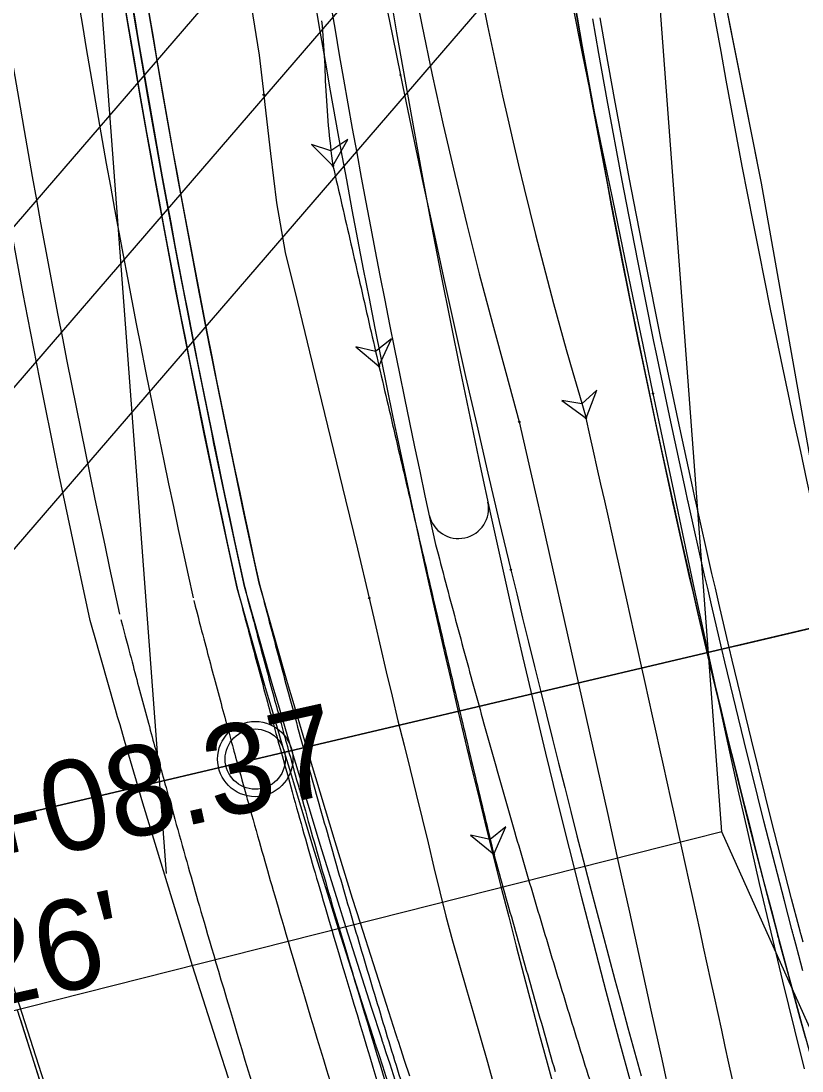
# Model space of a CAD drawing. Extents: x -70 to 701944, y -4 to 666871.
# Drawn here: x 668167.6 to 668219.5, y 656196.7 to 656266.5 of the extents above; entities that cross this region are included whole.
import ezdxf

# ---------------------------------------------------------------- set-up
doc = ezdxf.new("R2010")
doc.units = 0
for name, color, linetype in [('R_Detour', 7, 'Continuous'), ('R_Drive', 7, 'Continuous'), ('R_Horz Alg', 7, 'Continuous'), ('R_Horz Alg Annot', 7, 'Continuous'), ('R_No Plot', 7, 'Continuous'), ('R_Proposed Road', 7, 'Continuous'), ('R_Striping', 7, 'Continuous'), ('R_Water', 7, 'Continuous'), ('T_Indications', 7, 'Continuous'), ('T_Vehicle Path Lt Major', 7, 'Continuous'), ('T_Vehicle Path Rt', 7, 'Continuous')]:
    doc.layers.add(name, color=color, linetype=linetype)

msp = doc.modelspace()

# ---------------------------------------------------------------- linework, layer by layer
at = {"layer": 'R_Detour'}
msp.add_line((668141.731, 656207.682), (668219.062, 656225.912), dxfattribs=at)
at = {"layer": 'R_Drive'}
msp.add_lwpolyline([(668180.793, 656161.438), (668178.785, 656166.887), (668177.31, 656170.972), (668176.8, 656172.4), (668174.873, 656177.884), (668173.732, 656181.194), (668172.97, 656183.43), (668171.127, 656188.939), (668170.905, 656189.612), (668170.293, 656191.475), (668169.304, 656194.526), (668167.54, 656200.075)], dxfattribs=at)
at = {"layer": 'R_Horz Alg'}
for p, q in [((668214.129, 656212.597), (668204.795, 656337.586)), ((668265.354, 656098.207), (668214.129, 656212.597))]:
    msp.add_line(p, q, dxfattribs=at)
msp.add_lwpolyline([(668215.102, 656224.978), (668228.728, 656228.191)], dxfattribs=at)
msp.add_arc((668919.004, 656390.918), 716.197, 184.270523, 204.123313, dxfattribs=at)
at = {"layer": 'R_Horz Alg Annot'}
msp.add_lwpolyline([(668214.129, 656212.597), (668025.36, 656164.842)], dxfattribs=at)
at = {"layer": 'R_No Plot'}
for p, q in [((668177.231, 656209.842), (668160.778, 656430.175)), ((668146.592, 656218.335), (668259.536, 656349.509))]:
    msp.add_line(p, q, dxfattribs=at)
for points in [[(668203.487, 656355.108), (668251.852, 656358.719), (668253.161, 656341.197), (668253.893, 656332.226), (668254.707, 656323.663), (668256.989, 656304.018), (668259.175, 656288.746), (668262.093, 656271.387), (668265.097, 656255.918), (668267.006, 656246.759), (668268.493, 656237.565), (668221.915, 656226.584), (668216.775, 656255.73), (668213.367, 656272.838), (668209.96, 656289.947), (668208.341, 656303.042), (668205.828, 656325.201), (668204.769, 656337.932)], [(668145.584, 656319.648), (668148.917, 656289.832), (668153.337, 656260.517), (668160.437, 656224.08), (668163.658, 656212.851), (668221.915, 656226.584), (668216.775, 656255.73), (668209.96, 656289.947), (668206.722, 656316.137), (668205.828, 656325.201), (668149.946, 656320.05)], [(668163.658, 656212.851), (668174.905, 656177.818), (668188.213, 656142.348), (668200.781, 656111.402), (668251.57, 656131.168), (668244.19, 656150.993), (668237.799, 656169.607), (668229.783, 656196.07), (668221.915, 656226.584)]]:
    msp.add_lwpolyline(points, close=True, dxfattribs=at)
msp.add_circle((668183.124, 656217.44), 2.5, dxfattribs=at)
at = {"layer": 'R_Proposed Road'}
for points in [[(668219.702, 656198.856), (668219.335, 656200.197), (668218.975, 656201.524), (668218.715, 656202.488), (668218.621, 656202.836), (668218.549, 656203.105), (668218.274, 656204.134), (668218.077, 656204.876), (668217.947, 656205.365), (668217.934, 656205.415), (668217.921, 656205.463), (668217.916, 656205.483), (668217.913, 656205.492), (668217.908, 656205.512), (668217.882, 656205.61), (668217.817, 656205.855), (668217.315, 656207.769), (668215.955, 656213.059), (668215.547, 656214.68), (668214.636, 656218.36), (668213.356, 656223.671), (668213.155, 656224.519), (668212.464, 656227.477), (668212.237, 656228.464), (668212.116, 656228.991), (668212.011, 656229.451), (668210.916, 656234.32), (668210.901, 656234.391), (668210.735, 656235.142), (668209.757, 656239.658), (668208.784, 656244.293), (668208.638, 656245.004), (668207.559, 656250.359), (668206.806, 656254.223), (668206.52, 656255.722), (668205.522, 656261.093), (668204.967, 656264.18), (668204.564, 656266.471), (668203.647, 656271.856)], [(668192.426, 656196.101), (668192.08, 656197.151), (668191.831, 656197.909), (668191.667, 656198.41), (668191.651, 656198.461), (668191.635, 656198.51), (668191.628, 656198.53), (668191.625, 656198.54), (668191.618, 656198.56), (668191.586, 656198.66), (668191.504, 656198.91), (668190.869, 656200.866), (668189.145, 656206.277), (668188.625, 656207.935), (668187.46, 656211.703), (668185.816, 656217.143), (668185.557, 656218.013), (668184.664, 656221.046), (668184.369, 656222.059), (668184.212, 656222.599), (668184.076, 656223.071), (668182.649, 656228.068), (668182.629, 656228.141), (668182.412, 656228.913), (668181.395, 656233.609), (668180.383, 656238.429), (668180.231, 656239.17), (668179.109, 656244.739), (668178.326, 656248.757), (668178.029, 656250.316), (668176.99, 656255.901), (668176.413, 656259.112), (668175.995, 656261.494), (668175.041, 656267.095)], [(668193.392, 656196.359), (668193.046, 656197.409), (668192.797, 656198.166), (668192.634, 656198.665), (668192.617, 656198.717), (668192.601, 656198.765), (668192.595, 656198.785), (668192.592, 656198.795), (668192.585, 656198.815), (668192.552, 656198.915), (668192.471, 656199.165), (668191.837, 656201.119), (668190.114, 656206.522), (668189.595, 656208.178), (668188.431, 656211.94), (668186.789, 656217.374), (668186.531, 656218.243), (668185.638, 656221.272), (668185.344, 656222.283), (668185.187, 656222.822), (668185.05, 656223.294), (668183.626, 656228.284), (668183.605, 656228.357), (668183.389, 656229.128), (668182.373, 656233.818), (668181.363, 656238.631), (668181.21, 656239.371), (668180.09, 656244.932), (668179.308, 656248.945), (668179.011, 656250.502), (668177.974, 656256.08), (668177.398, 656259.287), (668176.98, 656261.666), (668176.027, 656267.259)], [(668191.943, 656195.971), (668191.597, 656197.022), (668191.348, 656197.781), (668191.184, 656198.282), (668191.167, 656198.333), (668191.151, 656198.382), (668191.145, 656198.402), (668191.141, 656198.412), (668191.135, 656198.432), (668191.102, 656198.532), (668191.021, 656198.782), (668190.386, 656200.74), (668188.66, 656206.154), (668188.14, 656207.814), (668186.975, 656211.584), (668185.33, 656217.028), (668185.071, 656217.899), (668184.177, 656220.934), (668183.882, 656221.947), (668183.725, 656222.487), (668183.588, 656222.96), (668182.161, 656227.96), (668182.141, 656228.033), (668181.924, 656228.805), (668180.906, 656233.505), (668179.894, 656238.328), (668179.741, 656239.069), (668178.618, 656244.642), (668177.835, 656248.663), (668177.537, 656250.223), (668176.499, 656255.812), (668175.921, 656259.025), (668175.502, 656261.409), (668174.548, 656267.013)], [(668219.515, 656203.364), (668219.24, 656204.391), (668219.043, 656205.132), (668218.914, 656205.621), (668218.9, 656205.671), (668218.888, 656205.719), (668218.882, 656205.738), (668218.88, 656205.748), (668218.875, 656205.768), (668218.849, 656205.865), (668218.784, 656206.11), (668218.283, 656208.021), (668216.925, 656213.305), (668216.517, 656214.923), (668215.607, 656218.598), (668214.329, 656223.901), (668214.129, 656224.749), (668213.439, 656227.703), (668213.211, 656228.688), (668213.091, 656229.214), (668212.986, 656229.674), (668211.893, 656234.536), (668211.877, 656234.607), (668211.712, 656235.357), (668210.735, 656239.866), (668209.764, 656244.495), (668209.617, 656245.206), (668208.54, 656250.553), (668207.788, 656254.412), (668207.503, 656255.909), (668206.506, 656261.272), (668205.952, 656264.355), (668205.55, 656266.643)], [(668219.526, 656205.261), (668219.397, 656205.749), (668219.384, 656205.799), (668219.371, 656205.847), (668219.366, 656205.866), (668219.363, 656205.876), (668219.358, 656205.895), (668219.332, 656205.993), (668219.268, 656206.237), (668218.766, 656208.147), (668217.41, 656213.427), (668217.002, 656215.045), (668216.093, 656218.717), (668214.815, 656224.016), (668214.615, 656224.863), (668213.926, 656227.815), (668213.699, 656228.8), (668213.578, 656229.325), (668213.473, 656229.785), (668212.381, 656234.644), (668212.365, 656234.714), (668212.2, 656235.464), (668211.224, 656239.971), (668210.253, 656244.596), (668210.107, 656245.306), (668209.03, 656250.65), (668208.279, 656254.506), (668207.994, 656256.002), (668206.998, 656261.361), (668206.444, 656264.442), (668206.042, 656266.728)], [(668181.353, 656196.231), (668180.71, 656198.214), (668178.965, 656203.701), (668178.44, 656205.384), (668177.262, 656209.204), (668175.599, 656214.722), (668175.337, 656215.604), (668174.438, 656218.681), (668174.138, 656219.707), (668173.977, 656220.254), (668173.841, 656220.734), (668172.397, 656225.801), (668172.376, 656225.875), (668172.157, 656226.657), (668171.126, 656231.419), (668170.1, 656236.306), (668169.945, 656237.057), (668168.808, 656242.704), (668168.014, 656246.778), (668167.713, 656248.359), (668166.66, 656254.022)], [(668169.099, 656195.184), (668167.332, 656200.758)]]:
    msp.add_lwpolyline(points, dxfattribs=at)
for radius in [707.197, 725.197]:
    msp.add_arc((668919.004, 656390.918), radius, 184.270523, 204.123313, dxfattribs=at)
at = {"layer": 'R_Striping'}
for centre, radius, start, end in [((668919.004, 656390.918), 737.197, 184.194321, 200.430569), ((668919.004, 656390.918), 741.197, 184.194564, 192.404344), ((668196.632, 656234.102), 2, 192.88532, 11.92337)]:
    msp.add_arc(centre, radius, start, end, dxfattribs=at)
msp.add_open_spline([(668195.109, 656231.702), (668195.55, 656230.027), (668196.43, 656226.678), (668197.795, 656221.667), (668199.192, 656216.667), (668200.624, 656211.678), (668202.091, 656206.7), (668203.592, 656201.735), (668205.127, 656196.781), (668206.697, 656191.84), (668208.301, 656186.91), (668209.94, 656181.994), (668211.612, 656177.091), (668213.318, 656172.201), (668215.058, 656167.324), (668216.831, 656162.461), (668218.638, 656157.611), (668220.479, 656152.776), (668222.353, 656147.955), (668224.26, 656143.149), (668226.199, 656138.357), (668227.519, 656135.174), (668228.18, 656133.583)], degree=3, dxfattribs=at)
at = {"layer": 'R_Water'}
for p, q in [((668254.821, 656354.76), (668141.288, 656222.903)), ((668265.43, 656345.625), (668151.897, 656213.768))]:
    msp.add_line(p, q, dxfattribs=at)
msp.add_circle((668183.124, 656217.44), 2, dxfattribs=at)
at = {"layer": 'T_Indications'}
for radius in [754.697, 754.197, 753.197, 762.697, 757.697]:
    msp.add_arc((668919.004, 656390.918), radius, 184.901486, 192.404344, dxfattribs=at)
for points in [[(668181.939, 656228.743), (668182.495, 656226.621), (668183.053, 656224.495), (668184.196, 656220.248), (668184.778, 656218.129), (668186.549, 656211.776), (668187.767, 656207.551), (668191.531, 656194.91), (668194.188, 656186.527), (668199.794, 656169.858), (668202.743, 656161.573), (668207.384, 656149.226), (668208.967, 656145.124), (668211.395, 656138.993), (668212.212, 656136.953), (668213.869, 656132.878), (668214.709, 656130.847), (668215.549, 656128.82)], [(668182.422, 656228.87), (668182.979, 656226.748), (668183.536, 656224.623), (668184.679, 656220.379), (668185.26, 656218.261), (668187.03, 656211.913), (668188.247, 656207.691), (668192.008, 656195.058), (668194.663, 656186.68), (668200.266, 656170.023), (668203.213, 656161.743), (668207.851, 656149.405), (668209.433, 656145.306), (668211.859, 656139.179), (668212.676, 656137.14), (668214.331, 656133.068), (668215.171, 656131.038), (668216.011, 656129.011)], [(668183.389, 656229.124), (668183.836, 656227.422), (668184.728, 656224.018), (668186.112, 656218.926), (668187.528, 656213.843), (668188.981, 656208.773), (668190.468, 656203.714), (668191.99, 656198.667), (668193.548, 656193.632), (668195.14, 656188.609), (668196.767, 656183.6), (668198.429, 656178.603), (668200.125, 656173.619), (668201.856, 656168.648), (668203.621, 656163.691), (668205.42, 656158.748), (668207.253, 656153.819), (668209.121, 656148.904), (668211.022, 656144.003), (668212.958, 656139.118), (668214.925, 656134.247), (668216.265, 656131.011), (668216.934, 656129.394)], [(668179.037, 656227.982), (668179.593, 656225.86), (668180.154, 656223.724), (668181.302, 656219.458), (668181.886, 656217.331), (668183.664, 656210.954), (668184.887, 656206.712), (668188.665, 656194.02), (668191.333, 656185.603), (668196.961, 656168.868), (668199.922, 656160.55), (668204.582, 656148.154), (668206.172, 656144.034), (668208.609, 656137.881), (668209.428, 656135.836), (668211.094, 656131.736), (668211.938, 656129.7), (668212.777, 656127.672)], [(668174.2, 656226.713), (668174.757, 656224.591), (668175.321, 656222.44), (668176.478, 656218.143), (668177.066, 656216.003), (668178.855, 656209.583), (668180.086, 656205.313), (668183.89, 656192.538), (668186.575, 656184.065), (668192.241, 656167.219), (668195.221, 656158.846), (668199.912, 656146.368), (668201.513, 656142.217), (668203.965, 656136.028), (668204.788, 656133.973), (668206.47, 656129.834), (668207.318, 656127.787), (668208.157, 656125.76)]]:
    msp.add_open_spline(points, degree=3, dxfattribs=at)
at = {"layer": 'T_Vehicle Path Lt Major'}
for points in [[(668198.024, 656310.552), (668198.233, 656307.172), (668198.415, 656303.791), (668198.629, 656300.42), (668198.918, 656297.065), (668199.245, 656293.718), (668199.706, 656290.377), (668200.339, 656287.056), (668200.97, 656283.788), (668201.604, 656280.545), (668202.244, 656277.302), (668202.89, 656274.062), (668203.541, 656270.823), (668204.196, 656267.586), (668204.856, 656264.352), (668205.518, 656261.119), (668206.184, 656257.889), (668206.853, 656254.661), (668207.524, 656251.434), (668208.198, 656248.204), (668208.875, 656244.974), (668209.553, 656241.743)], [(668187.665, 656309.168), (668188.188, 656305.928), (668188.711, 656302.686), (668189.235, 656299.441), (668189.76, 656296.188), (668190.285, 656292.932), (668190.668, 656289.651), (668190.878, 656286.341), (668191.277, 656282.993), (668191.788, 656279.633), (668192.335, 656276.278), (668192.919, 656272.93), (668193.538, 656269.588), (668194.194, 656266.253), (668194.886, 656262.925), (668195.613, 656259.604), (668196.377, 656256.292), (668197.176, 656252.988), (668198.01, 656249.693), (668198.881, 656246.407), (668199.786, 656243.131), (668200.669, 656239.854)], [(668209.553, 656241.743), (668210.232, 656238.513), (668210.918, 656235.262), (668211.607, 656231.997), (668212.299, 656228.732), (668212.996, 656225.467), (668213.7, 656222.204), (668214.412, 656218.943), (668215.134, 656215.684), (668215.868, 656212.427), (668216.615, 656209.173), (668217.377, 656205.923), (668218.154, 656202.676), (668218.948, 656199.433), (668219.597, 656196.842)], [(668200.669, 656239.854), (668201.42, 656236.554), (668202.164, 656233.283), (668202.901, 656230.031), (668203.636, 656226.778), (668204.367, 656223.525), (668205.097, 656220.272), (668205.823, 656217.018), (668206.548, 656213.763), (668207.269, 656210.508), (668207.989, 656207.252), (668208.705, 656203.996), (668209.42, 656200.74), (668210.132, 656197.483), (668210.7, 656194.877)]]:
    msp.add_lwpolyline(points, dxfattribs=at)
msp.add_lwpolyline([(668205.107, 656240.104), (668205.821, 656241.972), (668204.822, 656241.062), (668203.487, 656241.277)], close=True, dxfattribs=at)
for centre in [(668209.553, 656241.743), (668209.553, 656241.743), (668200.669, 656239.854), (668200.669, 656239.854), (668205.107, 656240.104), (668205.107, 656240.104)]:
    msp.add_circle(centre, 0.0417, dxfattribs=at)
for centre, radius, start, end in [((668502.803, 656328.666), 310.59, 187.22713, 196.5674), ((663153.359, 655099.466), 5178.919, 11.926242, 12.723498)]:
    msp.add_arc(centre, radius, start, end, dxfattribs=at)
at = {"layer": 'T_Vehicle Path Rt'}
for points in [[(668187.781, 656296.53), (668187.959, 656295.206), (668188.407, 656291.899), (668188.861, 656288.594), (668189.32, 656285.291), (668189.771, 656281.987), (668190.182, 656278.676), (668190.561, 656275.361), (668190.957, 656272.051), (668191.591, 656268.787), (668192.245, 656265.528), (668192.778, 656262.909)], [(668177.976, 656295.06), (668178.207, 656293.752), (668178.787, 656290.48), (668179.367, 656287.206), (668179.948, 656283.93), (668180.529, 656280.651), (668181.11, 656277.37), (668181.692, 656274.09), (668182.272, 656270.816), (668182.853, 656267.536), (668183.38, 656264.244), (668183.69, 656261.606)], [(668187.527, 656266.516), (668187.561, 656266.185), (668187.592, 656265.853), (668187.62, 656265.521), (668187.647, 656265.188), (668187.67, 656264.856), (668187.692, 656264.523), (668187.711, 656264.19), (668187.727, 656263.858), (668187.741, 656263.524), (668187.753, 656263.191), (668187.765, 656262.858), (668187.779, 656262.525), (668187.794, 656262.192), (668187.811, 656261.859), (668187.83, 656261.526), (668187.85, 656261.194), (668187.872, 656260.861), (668187.896, 656260.529), (668187.922, 656260.196), (668187.949, 656259.864), (668187.979, 656259.532), (668188.01, 656259.2), (668188.044, 656258.869), (668188.079, 656258.537), (668188.116, 656258.206), (668188.156, 656257.875), (668188.197, 656257.544), (668188.241, 656257.214), (668188.287, 656256.884)], [(668192.778, 656262.909), (668192.913, 656262.252), (668193.598, 656258.949), (668194.291, 656255.661), (668194.983, 656252.439), (668195.677, 656249.259), (668196.385, 656246.068), (668197.106, 656242.868), (668197.84, 656239.663), (668198.585, 656236.456), (668199.342, 656233.244), (668200.111, 656230.03)], [(668183.69, 656261.606), (668183.767, 656260.951), (668184.148, 656257.705), (668184.532, 656254.428), (668185.114, 656251.118), (668185.932, 656247.815), (668186.738, 656244.522), (668187.535, 656241.236), (668188.327, 656237.956), (668189.123, 656234.682), (668189.913, 656231.413), (668190.699, 656228.148)], [(668188.287, 656256.884), (668188.362, 656256.559), (668188.436, 656256.234), (668188.511, 656255.909), (668188.586, 656255.584), (668188.661, 656255.259), (668188.735, 656254.935), (668188.81, 656254.61), (668188.885, 656254.285), (668188.96, 656253.96), (668189.034, 656253.635), (668189.109, 656253.31), (668189.184, 656252.985), (668189.258, 656252.661), (668189.333, 656252.336), (668189.408, 656252.011), (668189.482, 656251.686), (668189.557, 656251.361), (668189.631, 656251.036), (668189.706, 656250.711), (668189.78, 656250.386), (668189.855, 656250.062), (668189.93, 656249.737), (668190.004, 656249.412), (668190.079, 656249.087), (668190.153, 656248.762), (668190.228, 656248.437), (668190.302, 656248.112), (668190.377, 656247.787), (668190.451, 656247.462), (668190.526, 656247.137), (668190.6, 656246.813), (668190.675, 656246.488), (668190.749, 656246.163), (668190.824, 656245.838), (668190.898, 656245.513), (668190.973, 656245.188), (668191.047, 656244.863), (668191.122, 656244.538), (668191.196, 656244.213), (668191.271, 656243.888), (668191.345, 656243.564)], [(668191.345, 656243.564), (668191.421, 656243.239), (668191.496, 656242.914), (668191.572, 656242.59), (668191.648, 656242.265), (668191.723, 656241.94), (668191.799, 656241.616), (668191.874, 656241.291), (668191.95, 656240.966), (668192.026, 656240.642), (668192.101, 656240.317), (668192.177, 656239.992), (668192.252, 656239.668), (668192.328, 656239.343), (668192.404, 656239.018), (668192.479, 656238.694), (668192.555, 656238.369), (668192.631, 656238.045), (668192.706, 656237.72), (668192.782, 656237.395), (668192.858, 656237.071), (668192.933, 656236.746), (668193.009, 656236.421), (668193.085, 656236.097), (668193.161, 656235.772), (668193.236, 656235.448), (668193.312, 656235.123), (668193.388, 656234.798), (668193.464, 656234.474), (668193.539, 656234.149), (668193.615, 656233.825), (668193.691, 656233.5), (668193.767, 656233.175), (668193.843, 656232.851), (668193.919, 656232.526), (668193.994, 656232.202), (668194.07, 656231.877), (668194.146, 656231.552), (668194.222, 656231.228), (668194.298, 656230.903), (668194.374, 656230.579), (668194.45, 656230.254), (668194.526, 656229.93), (668194.602, 656229.605), (668194.678, 656229.281), (668194.752, 656228.956), (668194.828, 656228.631), (668194.904, 656228.306), (668194.98, 656227.982), (668195.056, 656227.657), (668195.132, 656227.333), (668195.209, 656227.008), (668195.285, 656226.684), (668195.361, 656226.359), (668195.437, 656226.035), (668195.513, 656225.71), (668195.589, 656225.386), (668195.666, 656225.061), (668195.742, 656224.737), (668195.818, 656224.412), (668195.894, 656224.088), (668195.971, 656223.763), (668196.047, 656223.439), (668196.123, 656223.114), (668196.2, 656222.79), (668196.276, 656222.465), (668196.353, 656222.141), (668196.429, 656221.817), (668196.506, 656221.492), (668196.582, 656221.168), (668196.659, 656220.843), (668196.736, 656220.519), (668196.812, 656220.194), (668196.889, 656219.87), (668196.966, 656219.546), (668197.042, 656219.221), (668197.119, 656218.897), (668197.196, 656218.573), (668197.273, 656218.248), (668197.349, 656217.924), (668197.426, 656217.6), (668197.503, 656217.275), (668197.58, 656216.951), (668197.657, 656216.626), (668197.734, 656216.302), (668197.811, 656215.978), (668197.888, 656215.654), (668197.965, 656215.329), (668198.042, 656215.005), (668198.119, 656214.681), (668198.197, 656214.356), (668198.274, 656214.032), (668198.351, 656213.708), (668198.429, 656213.384), (668198.506, 656213.059), (668198.584, 656212.735), (668198.661, 656212.411), (668198.739, 656212.087), (668198.816, 656211.763), (668198.894, 656211.439), (668198.972, 656211.114)], [(668200.111, 656230.03), (668200.5, 656228.423), (668200.891, 656226.815), (668201.284, 656225.206), (668201.68, 656223.598), (668202.077, 656221.989), (668202.475, 656220.381), (668202.876, 656218.773), (668203.279, 656217.166), (668203.685, 656215.558), (668204.093, 656213.951), (668204.504, 656212.344), (668204.918, 656210.738), (668205.336, 656209.133), (668205.754, 656207.536), (668206.174, 656205.944), (668206.598, 656204.352), (668207.025, 656202.76), (668207.456, 656201.167), (668207.89, 656199.574), (668208.328, 656197.981), (668208.77, 656196.388)], [(668190.699, 656228.148), (668191.075, 656226.513), (668191.449, 656224.879), (668191.83, 656223.247), (668192.217, 656221.617), (668192.61, 656219.989), (668193.009, 656218.362), (668193.412, 656216.737), (668193.821, 656215.113), (668194.217, 656213.488), (668194.608, 656211.861), (668195, 656210.236), (668195.393, 656208.61), (668195.787, 656206.986), (668196.226, 656205.365), (668196.696, 656203.748), (668197.165, 656202.132), (668197.634, 656200.517), (668198.102, 656198.904), (668198.555, 656197.288), (668199.002, 656195.671)], [(668198.972, 656211.114), (668199.061, 656210.793), (668199.151, 656210.472), (668199.241, 656210.151), (668199.331, 656209.83), (668199.421, 656209.509), (668199.511, 656209.188), (668199.601, 656208.868), (668199.691, 656208.547), (668199.781, 656208.226), (668199.871, 656207.905), (668199.962, 656207.584), (668200.052, 656207.263), (668200.142, 656206.942), (668200.233, 656206.621), (668200.323, 656206.3), (668200.413, 656205.98), (668200.504, 656205.659), (668200.594, 656205.338), (668200.685, 656205.017), (668200.775, 656204.696), (668200.866, 656204.376), (668200.956, 656204.055), (668201.047, 656203.734), (668201.137, 656203.413), (668201.228, 656203.092), (668201.319, 656202.772), (668201.409, 656202.451), (668201.5, 656202.13), (668201.591, 656201.809), (668201.682, 656201.489), (668201.773, 656201.168), (668201.863, 656200.847), (668201.954, 656200.527), (668202.045, 656200.206), (668202.136, 656199.885), (668202.227, 656199.564), (668202.318, 656199.244), (668202.409, 656198.923), (668202.5, 656198.603), (668202.592, 656198.282), (668202.683, 656197.961), (668202.774, 656197.641), (668202.865, 656197.32), (668202.956, 656196.999), (668203.048, 656196.679)]]:
    msp.add_lwpolyline(points, dxfattribs=at)
for points in [[(668188.287, 656256.884), (668189.274, 656258.623), (668188.149, 656257.874), (668186.863, 656258.287)], [(668191.345, 656243.564), (668192.177, 656245.383), (668191.121, 656244.538), (668189.803, 656244.837)], [(668198.972, 656211.114), (668199.785, 656212.941), (668198.738, 656212.087), (668197.418, 656212.373)]]:
    msp.add_lwpolyline(points, close=True, dxfattribs=at)
for centre in [(668192.778, 656262.909), (668192.778, 656262.909), (668183.69, 656261.606), (668183.69, 656261.606), (668188.287, 656256.884), (668188.287, 656256.884), (668191.345, 656243.564), (668191.345, 656243.564), (668200.111, 656230.03), (668200.111, 656230.03), (668190.699, 656228.148), (668190.699, 656228.148), (668198.972, 656211.114), (668198.972, 656211.114)]:
    msp.add_circle(centre, 0.0417, dxfattribs=at)
msp.add_arc((668919.004, 656390.918), 742.197, 184.270523, 204.123313, dxfattribs=at)

# ---------------------------------------------------------------- texts
at = {"layer": 'R_No Plot'}
for s, p in [('130+08.37 ', (668151.946, 656207.044)), ("75.26' ", (668153.909, 656198.261))]:
    msp.add_text(s, height=6, rotation=12.59492, dxfattribs=at).set_placement(p)

doc.saveas('drawing.dxf')
